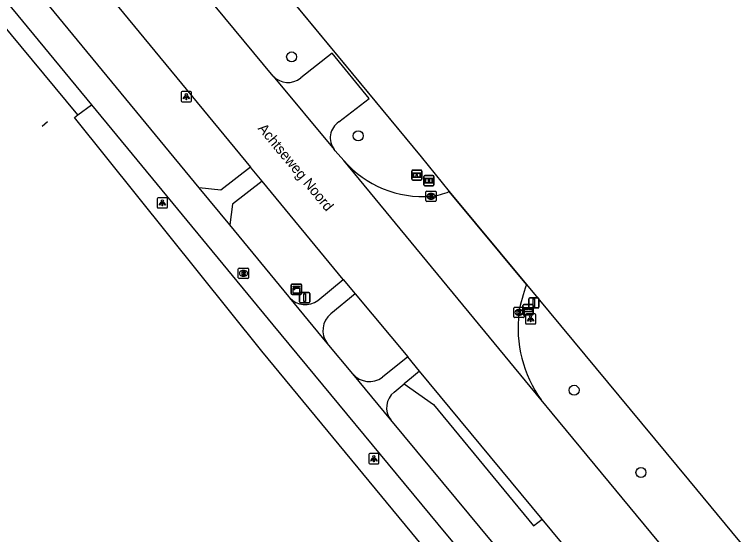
# Model space of a CAD drawing. Extents: x 156141 to 158132, y 385651 to 388399.
# Drawn here: x 157235 to 157305.1, y 386871.2 to 386921.8 of the extents above; entities that cross this region are included whole.
import ezdxf

# ---------------------------------------------------------------- set-up
doc = ezdxf.new("R2010")
doc.units = 0
for name, color, linetype in [('IMGEO_Berm_gesloten', 7, 'Continuous'), ('IMGEO_Berm_groen', 7, 'Continuous'), ('IMGEO_Boom', 7, 'Continuous'), ('IMGEO_Brievenbus', 7, 'Continuous'), ('IMGEO_Fietspad_gesloten', 7, 'Continuous'), ('IMGEO_Fietspad_open', 7, 'Continuous'), ('IMGEO_Groenvoorziening', 7, 'Continuous'), ('IMGEO_Hek', 7, 'Continuous'), ('IMGEO_Informatiebord', 7, 'Continuous'), ('IMGEO_Kast', 7, 'Continuous'), ('IMGEO_Kolk', 7, 'Continuous'), ('IMGEO_Lichtpunt', 7, 'Continuous'), ('IMGEO_Openbare_ruimte_label', 7, 'Continuous'), ('IMGEO_Rijbaan_lokaal_gesloten', 7, 'Continuous'), ('IMGEO_Rijbaan_lokaal_open', 7, 'Continuous'), ('IMGEO_Rioolput', 7, 'Continuous'), ('IMGEO_Verkeersbordpaal', 7, 'Continuous'), ('IMGEO_Voetpad_open', 7, 'Continuous')]:
    doc.layers.add(name, color=color, linetype=linetype)

msp = doc.modelspace()

# ---------------------------------------------------------------- linework, layer by layer
at = {"layer": 'IMGEO_Berm_gesloten'}
msp.add_lwpolyline([(157272.933, 386885.886), (157275.785, 386883.861), (157285.512, 386872.07), (157286.349, 386872.725)], dxfattribs=at)
at = {"layer": 'IMGEO_Berm_groen'}
for points in [[(157241.165, 386912.065), (157168.24, 387000), (157137.214, 387037.654), (157129.348, 387046.654), (157129.178, 387046.529), (157127.008, 387049.143), (157127.143, 387049.253), (157124.865, 387052.05), (157124.727, 387051.938), (157091.865, 387091.792), (157084.853, 387100.371), (157072.384, 387115.628), (157065.427, 387124.277), (157056.488, 387135.39)], [(157257.772, 386928.303), (157274.585, 386907.978), (157277.321, 386904.607)], [(157241.165, 386912.065), (157242.501, 386913.018)], [(157284.844, 386895.533), (157300.587, 386876.543), (157345.88, 386821.789), (157383.128, 386776.761), (157405.264, 386750), (157412.601, 386741.13)]]:
    msp.add_lwpolyline(points, dxfattribs=at)
at = {"layer": 'IMGEO_Boom'}
for centre in [(157261.983, 386917.689), (157268.465, 386910.01), (157289.466, 386885.257), (157295.977, 386877.255)]:
    msp.add_circle(centre, 0.489, dxfattribs=at)
at = {"layer": 'IMGEO_Brievenbus'}
for p, q in [((157284.495, 386892.666), (157284.495, 386893.507)), ((157284.495, 386893.507), (157284.495, 386892.666)), ((157284.57, 386893.591), (157285.411, 386893.591)), ((157285.411, 386893.591), (157284.57, 386893.591)), ((157285.495, 386893.516), (157285.495, 386892.675)), ((157285.495, 386892.675), (157285.495, 386893.516)), ((157284.939, 386893.198), (157284.662, 386893.198)), ((157284.662, 386893.114), (157284.939, 386893.114)), ((157285.331, 386893.198), (157285.054, 386893.198)), ((157285.054, 386893.114), (157285.331, 386893.114)), ((157285.42, 386892.591), (157284.579, 386892.591)), ((157284.579, 386892.591), (157285.42, 386892.591))]:
    msp.add_line(p, q, dxfattribs=at)
msp.add_lwpolyline([(157284.596, 386893.298), (157285.403, 386893.298), (157285.403, 386892.893), (157284.596, 386892.893), (157284.596, 386893.298)], dxfattribs=at)
for centre, radius, start, end in [((157284.573, 386893.513), 0.0779, 92.4484, 184.28452), ((157284.573, 386893.513), 0.0779, 92.4484, 184.28452), ((157285.417, 386893.513), 0.0779, 2.4484, 94.28452), ((157285.417, 386893.513), 0.0779, 2.4484, 94.28452), ((157284.573, 386892.669), 0.0779, 182.4484, 274.28452), ((157284.573, 386892.669), 0.0779, 182.4484, 274.28452), ((157284.692, 386893.156), 0.0519, 125.8089, 234.1911), ((157284.908, 386893.156), 0.0519, 305.8089, 54.1911), ((157285.085, 386893.156), 0.0519, 125.8089, 234.1911), ((157285.301, 386893.156), 0.0519, 305.8089, 54.1911), ((157285.417, 386892.669), 0.0779, 272.4484, 4.28452), ((157285.417, 386892.669), 0.0779, 272.4484, 4.28452)]:
    msp.add_arc(centre, radius, start, end, dxfattribs=at)
at = {"layer": 'IMGEO_Fietspad_gesloten'}
for points in [[(157164.67, 387007.384), (157170.76, 387000), (157242.501, 386913.018)], [(157252.995, 386904.943), (157193.011, 386977.75)], [(157242.501, 386913.018), (157260.151, 386891.618), (157276.215, 386872.22), (157291.723, 386853.572)], [(157255.954, 386901.352), (157252.995, 386904.943)], [(157261.8, 386894.257), (157261.703, 386894.374), (157255.954, 386901.352)], [(157265.439, 386889.847), (157261.8, 386894.257)], [(157267.939, 386886.841), (157265.439, 386889.847)], [(157271.628, 386882.378), (157267.939, 386886.841)], [(157295.329, 386853.774), (157294.671, 386854.555), (157291.271, 386858.658), (157287.92, 386862.757), (157271.628, 386882.378)]]:
    msp.add_lwpolyline(points, dxfattribs=at)
at = {"layer": 'IMGEO_Fietspad_open'}
for points in [[(157257.986, 386906.969), (157255.079, 386904.738), (157252.995, 386904.943)], [(157259.115, 386905.601), (157256.236, 386903.351), (157255.954, 386901.352)]]:
    msp.add_lwpolyline(points, dxfattribs=at)
at = {"layer": 'IMGEO_Groenvoorziening'}
msp.add_lwpolyline([(157288.716, 386853.161), (157259.099, 386889.064), (157240.867, 386911.803), (157241.165, 386912.065)], dxfattribs=at)
at = {"layer": 'IMGEO_Hek'}
for points in [[(157257.646, 386928.455), (157274.585, 386907.978)], [(157237.718, 386910.963), (157238.226, 386911.407)], [(157274.585, 386907.978), (157277.321, 386904.607)], [(157284.844, 386895.533), (157277.321, 386904.607)], [(157284.844, 386895.533), (157300.587, 386876.543)], [(157300.587, 386876.543), (157345.88, 386821.789)]]:
    msp.add_lwpolyline(points, dxfattribs=at)
at = {"layer": 'IMGEO_Informatiebord'}
for p, q in [((157273.768, 386906.688), (157274.558, 386906.688)), ((157274.558, 386906.688), (157273.768, 386906.688)), ((157273.668, 386905.788), (157273.668, 386906.588)), ((157273.668, 386906.588), (157273.668, 386905.788)), ((157274.658, 386906.588), (157274.658, 386905.788)), ((157274.658, 386905.788), (157274.658, 386906.588)), ((157274.845, 386905.256), (157274.845, 386906.056)), ((157274.845, 386906.056), (157274.845, 386905.256)), ((157274.945, 386906.156), (157275.735, 386906.156)), ((157275.735, 386906.156), (157274.945, 386906.156)), ((157275.835, 386906.056), (157275.835, 386905.256)), ((157275.835, 386905.256), (157275.835, 386906.056)), ((157274.558, 386905.688), (157273.768, 386905.688)), ((157273.768, 386905.688), (157274.558, 386905.688)), ((157275.735, 386905.156), (157274.945, 386905.156)), ((157274.945, 386905.156), (157275.735, 386905.156))]:
    msp.add_line(p, q, dxfattribs=at)
for points in [[(157273.769, 386906.42), (157274.557, 386906.42), (157274.557, 386905.956), (157273.769, 386905.956), (157273.769, 386906.42)], [(157273.834, 386906.355), (157273.834, 386906.021), (157274.109, 386906.021), (157274.11, 386906.234), (157274.214, 386906.235), (157274.215, 386906.021), (157274.492, 386906.021), (157274.492, 386906.355), (157274.216, 386906.355), (157274.216, 386906.275), (157274.11, 386906.275), (157274.11, 386906.355), (157273.834, 386906.355)], [(157274.946, 386905.888), (157275.734, 386905.888), (157275.734, 386905.424), (157274.946, 386905.424), (157274.946, 386905.888)], [(157275.011, 386905.823), (157275.011, 386905.489), (157275.286, 386905.489), (157275.287, 386905.702), (157275.391, 386905.703), (157275.392, 386905.489), (157275.669, 386905.489), (157275.669, 386905.823), (157275.393, 386905.823), (157275.393, 386905.743), (157275.287, 386905.743), (157275.287, 386905.823), (157275.011, 386905.823)]]:
    msp.add_lwpolyline(points, dxfattribs=at)
for centre, start, end in [((157273.768, 386906.588), 90, 180), ((157273.768, 386906.588), 90, 180), ((157274.558, 386906.588), 0, 90), ((157274.558, 386906.588), 360, 90), ((157274.945, 386906.056), 90, 180), ((157274.945, 386906.056), 90, 180), ((157275.735, 386906.056), 0, 90), ((157275.735, 386906.056), 360, 90), ((157273.768, 386905.788), 180, 270), ((157273.768, 386905.788), 180, 270), ((157274.558, 386905.788), 270, 0), ((157274.558, 386905.788), 270, 0), ((157274.945, 386905.256), 180, 270), ((157274.945, 386905.256), 180, 270), ((157275.735, 386905.256), 270, 0), ((157275.735, 386905.256), 270, 0)]:
    msp.add_arc(centre, 0.1, start, end, dxfattribs=at)
at = {"layer": 'IMGEO_Kast'}
for p, q in [((157261.943, 386894.665), (157261.943, 386895.506)), ((157261.943, 386895.506), (157261.943, 386894.665)), ((157262.018, 386895.59), (157262.859, 386895.59)), ((157262.859, 386895.59), (157262.018, 386895.59)), ((157262.943, 386895.515), (157262.943, 386894.674)), ((157262.943, 386894.674), (157262.943, 386895.515)), ((157262.868, 386894.59), (157262.027, 386894.59)), ((157262.027, 386894.59), (157262.868, 386894.59))]:
    msp.add_line(p, q, dxfattribs=at)
for points in [[(157262.138, 386895.38), (157262.738, 386895.38), (157262.738, 386895.295), (157262.138, 386895.295), (157262.138, 386895.38)], [(157262.138, 386895.205), (157262.738, 386895.205), (157262.738, 386894.716), (157262.138, 386894.716), (157262.138, 386895.205)]]:
    msp.add_lwpolyline(points, dxfattribs=at)
msp.add_circle((157262.222, 386895.054), 0.0377, dxfattribs=at)
for centre, start, end in [((157262.021, 386895.512), 92.4484, 184.28452), ((157262.021, 386895.512), 92.4484, 184.28452), ((157262.865, 386895.512), 2.4484, 94.28452), ((157262.865, 386895.512), 2.4484, 94.28452), ((157262.021, 386894.668), 182.4484, 274.28452), ((157262.021, 386894.668), 182.4484, 274.28452), ((157262.865, 386894.668), 272.4484, 4.28452), ((157262.865, 386894.668), 272.4484, 4.28452)]:
    msp.add_arc(centre, 0.0779, start, end, dxfattribs=at)
at = {"layer": 'IMGEO_Kolk'}
for p, q in [((157275.049, 386903.709), (157275.049, 386904.561)), ((157275.124, 386904.635), (157275.976, 386904.635)), ((157276.05, 386904.561), (157276.05, 386903.709)), ((157275.56, 386903.855), (157275.535, 386903.855)), ((157275.537, 386904.415), (157275.562, 386904.415)), ((157275.976, 386903.635), (157275.124, 386903.635)), ((157283.685, 386893.331), (157284.537, 386893.331)), ((157283.61, 386892.405), (157283.61, 386893.257)), ((157284.098, 386893.111), (157284.123, 386893.111)), ((157284.611, 386893.257), (157284.611, 386892.405)), ((157284.537, 386892.331), (157283.685, 386892.331)), ((157284.121, 386892.551), (157284.096, 386892.551))]:
    msp.add_line(p, q, dxfattribs=at)
for points in [[(157275.049, 386903.709), (157275.049, 386904.561)], [(157275.124, 386904.635), (157275.976, 386904.635)], [(157276.05, 386904.561), (157276.05, 386903.709)], [(157275.37, 386904.335), (157275.493, 386904.335), (157275.493, 386904.184), (157275.623, 386904.335), (157275.787, 386904.335), (157275.641, 386904.184), (157275.794, 386903.935), (157275.642, 386903.935), (157275.557, 386904.099), (157275.493, 386904.032), (157275.493, 386903.935), (157275.37, 386903.935), (157275.37, 386904.335)], [(157275.976, 386903.635), (157275.124, 386903.635)], [(157283.685, 386893.331), (157284.537, 386893.331)], [(157283.61, 386892.405), (157283.61, 386893.257)], [(157283.931, 386893.031), (157284.054, 386893.031), (157284.054, 386892.88), (157284.184, 386893.031), (157284.348, 386893.031), (157284.202, 386892.88), (157284.355, 386892.631), (157284.203, 386892.631), (157284.118, 386892.795), (157284.054, 386892.728), (157284.054, 386892.631), (157283.931, 386892.631), (157283.931, 386893.031)], [(157284.611, 386893.257), (157284.611, 386892.405)], [(157284.537, 386892.331), (157283.685, 386892.331)]]:
    msp.add_lwpolyline(points, dxfattribs=at)
for centre, start, end in [((157275.126, 386904.559), 91.55205, 178.44795), ((157275.126, 386904.559), 91.55205, 178.44795), ((157275.974, 386904.559), 1.55205, 88.44795), ((157275.974, 386904.559), 1.55205, 88.44795), ((157275.126, 386903.711), 181.55205, 268.44795), ((157275.126, 386903.711), 181.55205, 268.44795), ((157275.974, 386903.711), 271.55205, 358.44795), ((157275.974, 386903.711), 271.55205, 358.44795), ((157283.687, 386893.255), 91.55205, 178.44795), ((157283.687, 386893.255), 91.55205, 178.44795), ((157284.535, 386893.255), 1.55205, 88.44795), ((157284.535, 386893.255), 1.55205, 88.44795), ((157283.687, 386892.407), 181.55205, 268.44795), ((157283.687, 386892.407), 181.55205, 268.44795), ((157284.535, 386892.407), 271.55205, 358.44795), ((157284.535, 386892.407), 271.55205, 358.44795)]:
    msp.add_arc(centre, 0.0765, start, end, dxfattribs=at)
for centre, major_axis, ratio, start_param, end_param in [((157275.536, 386904.135), (-0.387, 0.002), 0.722429, 4.712389, 7.853982), ((157275.561, 386904.135), (-0.39, 0.002), 0.717154, 1.570796, 4.712389), ((157284.097, 386892.831), (-0.387, 0.002), 0.722429, 4.712389, 7.853982), ((157284.122, 386892.831), (-0.39, 0.002), 0.717154, 1.570796, 4.712389)]:
    msp.add_ellipse(centre, major_axis=major_axis, ratio=ratio, start_param=start_param, end_param=end_param, dxfattribs=at)
at = {"layer": 'IMGEO_Lichtpunt'}
for p, q in [((157251.239, 386914.235), (157251.239, 386913.428)), ((157251.239, 386914.235), (157251.239, 386913.428)), ((157252.141, 386914.33), (157251.333, 386914.33)), ((157252.141, 386914.33), (157251.333, 386914.33)), ((157252.235, 386913.428), (157252.235, 386914.235)), ((157252.235, 386913.428), (157252.235, 386914.235)), ((157251.333, 386913.334), (157252.141, 386913.334)), ((157251.333, 386913.334), (157252.141, 386913.334)), ((157248.906, 386903.896), (157248.906, 386903.089)), ((157248.906, 386903.896), (157248.906, 386903.089)), ((157249.808, 386903.991), (157249, 386903.991)), ((157249.808, 386903.991), (157249, 386903.991)), ((157249.902, 386903.089), (157249.902, 386903.896)), ((157249.902, 386903.089), (157249.902, 386903.896)), ((157249, 386902.995), (157249.808, 386902.995)), ((157249, 386902.995), (157249.808, 386902.995)), ((157284.736, 386892.61), (157284.736, 386891.803)), ((157284.736, 386892.61), (157284.736, 386891.803)), ((157285.638, 386892.705), (157284.83, 386892.705)), ((157285.638, 386892.705), (157284.83, 386892.705)), ((157285.732, 386891.803), (157285.732, 386892.61)), ((157285.732, 386891.803), (157285.732, 386892.61)), ((157284.83, 386891.709), (157285.638, 386891.709)), ((157284.83, 386891.709), (157285.638, 386891.709)), ((157269.487, 386879), (157269.487, 386878.193)), ((157269.487, 386879), (157269.487, 386878.193)), ((157270.389, 386879.095), (157269.581, 386879.095)), ((157270.389, 386879.095), (157269.581, 386879.095)), ((157270.483, 386878.193), (157270.483, 386879)), ((157270.483, 386878.193), (157270.483, 386879)), ((157269.581, 386878.099), (157270.389, 386878.099)), ((157269.581, 386878.099), (157270.389, 386878.099))]:
    msp.add_line(p, q, dxfattribs=at)
for points in [[(157251.613, 386913.899), (157251.652, 386913.871), (157251.464, 386913.609), (157251.426, 386913.636), (157251.613, 386913.899)], [(157251.715, 386913.851), (157251.762, 386913.851), (157251.762, 386913.529), (157251.715, 386913.529), (157251.715, 386913.851)], [(157251.825, 386913.871), (157251.863, 386913.898), (157252.05, 386913.636), (157252.011, 386913.608), (157251.825, 386913.871)], [(157249.28, 386903.56), (157249.319, 386903.532), (157249.131, 386903.27), (157249.093, 386903.297), (157249.28, 386903.56)], [(157249.382, 386903.512), (157249.429, 386903.512), (157249.429, 386903.19), (157249.382, 386903.19), (157249.382, 386903.512)], [(157249.492, 386903.532), (157249.53, 386903.559), (157249.717, 386903.297), (157249.678, 386903.269), (157249.492, 386903.532)], [(157285.11, 386892.274), (157285.149, 386892.246), (157284.961, 386891.984), (157284.923, 386892.011), (157285.11, 386892.274)], [(157285.212, 386892.226), (157285.259, 386892.226), (157285.259, 386891.904), (157285.212, 386891.904), (157285.212, 386892.226)], [(157285.322, 386892.246), (157285.36, 386892.273), (157285.547, 386892.011), (157285.508, 386891.983), (157285.322, 386892.246)], [(157269.861, 386878.664), (157269.9, 386878.636), (157269.712, 386878.374), (157269.674, 386878.401), (157269.861, 386878.664)], [(157269.963, 386878.616), (157270.01, 386878.616), (157270.01, 386878.294), (157269.963, 386878.294), (157269.963, 386878.616)], [(157270.073, 386878.636), (157270.111, 386878.663), (157270.298, 386878.401), (157270.259, 386878.373), (157270.073, 386878.636)]]:
    msp.add_lwpolyline(points, dxfattribs=at)
for centre in [(157251.738, 386914.033), (157249.405, 386903.694), (157285.235, 386892.408), (157269.986, 386878.798)]:
    msp.add_circle(centre, 0.0994, dxfattribs=at)
for centre, start, end in [((157251.333, 386914.235), 90, 180), ((157251.333, 386914.235), 90, 180), ((157252.141, 386914.235), 0, 90), ((157252.141, 386914.235), 0, 90), ((157251.333, 386913.428), 180, 270), ((157251.333, 386913.428), 180, 270), ((157252.141, 386913.428), 270, 0), ((157252.141, 386913.428), 270, 360), ((157249, 386903.896), 90, 180), ((157249, 386903.896), 90, 180), ((157249.808, 386903.896), 0, 90), ((157249.808, 386903.896), 0, 90), ((157249, 386903.089), 180, 270), ((157249, 386903.089), 180, 270), ((157249.808, 386903.089), 270, 0), ((157249.808, 386903.089), 270, 360), ((157284.83, 386892.61), 90, 180), ((157284.83, 386892.61), 90, 180), ((157285.638, 386892.61), 0, 90), ((157285.638, 386892.61), 0, 90), ((157284.83, 386891.803), 180, 270), ((157284.83, 386891.803), 180, 270), ((157285.638, 386891.803), 270, 0), ((157285.638, 386891.803), 270, 360), ((157269.581, 386879), 90, 180), ((157269.581, 386879), 90, 180), ((157270.389, 386879), 0, 90), ((157270.389, 386879), 0, 90), ((157269.581, 386878.193), 180, 270), ((157269.581, 386878.193), 180, 270), ((157270.389, 386878.193), 270, 0), ((157270.389, 386878.193), 270, 360)]:
    msp.add_arc(centre, 0.0946, start, end, dxfattribs=at)
at = {"layer": 'IMGEO_Rijbaan_lokaal_gesloten'}
for points in [[(157195.983, 386982.099), (157257.986, 386906.969)], [(157260.189, 386915.832), (157244.022, 386935.339), (157241.867, 386937.946)], [(157260.189, 386915.832), (157266.123, 386908.683)], [(157267.072, 386907.598), (157266.22, 386908.566), (157266.123, 386908.683)], [(157286.267, 386884.319), (157267.072, 386907.598)], [(157259.115, 386905.601), (157257.986, 386906.969)], [(157267.013, 386896.031), (157259.115, 386905.601)], [(157267.013, 386896.031), (157268.159, 386894.645)], [(157268.159, 386894.645), (157273.284, 386888.521)], [(157274.432, 386887.106), (157273.284, 386888.521)], [(157286.349, 386872.725), (157274.432, 386887.106)], [(157304.542, 386862.255), (157287.34, 386883.018), (157286.267, 386884.319)], [(157298.899, 386857.58), (157286.349, 386872.725)]]:
    msp.add_lwpolyline(points, dxfattribs=at)
at = {"layer": 'IMGEO_Rijbaan_lokaal_open'}
for points in [[(157266.574, 386911.363), (157269.513, 386913.654), (157265.941, 386918.061), (157262.862, 386915.645)], [(157277.321, 386904.607), (157284.844, 386895.533)]]:
    msp.add_lwpolyline(points, dxfattribs=at)
for centre, radius, start, end in [((157261.623, 386917.127), 1.932, 222.08115, 309.91519), ((157267.602, 386909.812), 1.86, 123.53058, 217.36455), ((157274.743, 386914.267), 10.165, 221.00242, 274.53007), ((157275.125, 386909.28), 5.163, 274.67384, 295.16891), ((157297.311, 386890.676), 13.38, 158.71511, 170.73159), ((157296.115, 386891.349), 12.1, 172.96663, 215.5236)]:
    msp.add_arc(centre, radius, start, end, dxfattribs=at)
at = {"layer": 'IMGEO_Rioolput'}
for p, q in [((157256.796, 386896.207), (157256.796, 386897.059)), ((157256.871, 386897.133), (157257.723, 386897.133)), ((157257.284, 386896.913), (157257.309, 386896.913)), ((157257.797, 386897.059), (157257.797, 386896.207)), ((157257.723, 386896.133), (157256.871, 386896.133)), ((157257.307, 386896.353), (157257.282, 386896.353))]:
    msp.add_line(p, q, dxfattribs=at)
for points in [[(157256.796, 386896.207), (157256.796, 386897.059)], [(157256.871, 386897.133), (157257.723, 386897.133)], [(157257.385, 386896.831), (157257.133, 386896.833), (157257.133, 386896.433)], [(157257.797, 386897.059), (157257.797, 386896.207)], [(157257.723, 386896.133), (157256.871, 386896.133)], [(157257.133, 386896.433), (157257.257, 386896.433), (157257.257, 386896.595), (157257.268, 386896.595)], [(157257.311, 386896.752), (157257.257, 386896.752), (157257.257, 386896.671)], [(157257.257, 386896.671), (157257.309, 386896.671)], [(157257.315, 386896.566), (157257.386, 386896.433), (157257.526, 386896.433), (157257.461, 386896.559)]]:
    msp.add_lwpolyline(points, dxfattribs=at)
for centre, radius, start, end in [((157256.873, 386897.057), 0.0765, 91.55205, 178.44795), ((157256.873, 386897.057), 0.0765, 91.55205, 178.44795), ((157257.384, 386896.721), 0.109, 350.36119, 89.41601), ((157257.721, 386897.057), 0.0765, 1.55205, 88.44795), ((157257.721, 386897.057), 0.0765, 1.55205, 88.44795), ((157256.873, 386896.209), 0.0765, 181.55205, 268.44795), ((157256.873, 386896.209), 0.0765, 181.55205, 268.44795), ((157257.267, 386896.542), 0.0533, 26.02933, 88.69889), ((157257.293, 386896.86), 0.19, 274.7715, 282.96867), ((157257.317, 386896.656), 0.0964, 77.00612, 93.18647), ((157257.331, 386896.713), 0.0378, 276.66336, 79.67722), ((157257.382, 386896.721), 0.112, 277.58423, 350.98172), ((157257.366, 386896.506), 0.108, 29.51342, 73.79051), ((157257.721, 386896.209), 0.0765, 271.55205, 358.44795), ((157257.721, 386896.209), 0.0765, 271.55205, 358.44795)]:
    msp.add_arc(centre, radius, start, end, dxfattribs=at)
for centre, major_axis, ratio, start_param, end_param in [((157257.283, 386896.633), (-0.387, 0.002), 0.722429, 4.712389, 7.853982), ((157257.308, 386896.633), (-0.39, 0.002), 0.717154, 1.570796, 4.712389)]:
    msp.add_ellipse(centre, major_axis=major_axis, ratio=ratio, start_param=start_param, end_param=end_param, dxfattribs=at)
at = {"layer": 'IMGEO_Verkeersbordpaal'}
for p, q in [((157262.853, 386894.775), (157263.643, 386894.775)), ((157263.643, 386894.775), (157262.853, 386894.775)), ((157262.753, 386893.875), (157262.753, 386894.675)), ((157262.753, 386894.675), (157262.753, 386893.875)), ((157263.743, 386894.675), (157263.743, 386893.875)), ((157263.743, 386893.875), (157263.743, 386894.675)), ((157285.062, 386893.363), (157285.062, 386894.163)), ((157285.062, 386894.163), (157285.062, 386893.363)), ((157285.162, 386894.263), (157285.952, 386894.263)), ((157285.952, 386894.263), (157285.162, 386894.263)), ((157286.052, 386894.163), (157286.052, 386893.363)), ((157286.052, 386893.363), (157286.052, 386894.163)), ((157263.643, 386893.775), (157262.853, 386893.775)), ((157262.853, 386893.775), (157263.643, 386893.775)), ((157285.952, 386893.263), (157285.162, 386893.263)), ((157285.162, 386893.263), (157285.952, 386893.263))]:
    msp.add_line(p, q, dxfattribs=at)
for points in [[(157263.173, 386894.65), (157263.323, 386894.65), (157263.323, 386893.9), (157263.173, 386893.9), (157263.173, 386894.65)], [(157285.482, 386894.138), (157285.632, 386894.138), (157285.632, 386893.388), (157285.482, 386893.388), (157285.482, 386894.138)]]:
    msp.add_lwpolyline(points, dxfattribs=at)
for centre, start, end in [((157262.853, 386894.675), 90, 180), ((157262.853, 386894.675), 90, 180), ((157263.643, 386894.675), 0, 90), ((157263.643, 386894.675), 360, 90), ((157285.162, 386894.163), 90, 180), ((157285.162, 386894.163), 90, 180), ((157285.952, 386894.163), 0, 90), ((157285.952, 386894.163), 360, 90), ((157262.853, 386893.875), 180, 270), ((157262.853, 386893.875), 180, 270), ((157263.643, 386893.875), 270, 0), ((157263.643, 386893.875), 270, 0), ((157285.162, 386893.363), 180, 270), ((157285.162, 386893.363), 180, 270), ((157285.952, 386893.363), 270, 0), ((157285.952, 386893.363), 270, 0)]:
    msp.add_arc(centre, 0.1, start, end, dxfattribs=at)
at = {"layer": 'IMGEO_Voetpad_open'}
for points in [[(157264.532, 386894.007), (157267.013, 386896.031)], [(157268.159, 386894.645), (157265.787, 386892.69)], [(157273.284, 386888.521), (157270.815, 386886.519)], [(157274.432, 386887.106), (157273.64, 386886.461), (157272.933, 386885.886)], [(157271.95, 386885.086), (157272.933, 386885.886)]]:
    msp.add_lwpolyline(points, dxfattribs=at)
for centre, radius, start, end in [((157263.3, 386895.594), 2.009, 221.70699, 307.83608), ((157267.093, 386891.087), 2.067, 129.17842, 216.86433), ((157269.551, 386888.235), 2.131, 220.84969, 306.37372), ((157273.177, 386883.567), 1.953, 128.92788, 217.51007)]:
    msp.add_arc(centre, radius, start, end, dxfattribs=at)

# ---------------------------------------------------------------- texts
at = {"layer": 'IMGEO_Openbare_ruimte_label'}
msp.add_text('Achtseweg Noord', height=1, rotation=309.64417, dxfattribs=at).set_placement((157258.639, 386910.706))

doc.saveas('drawing.dxf')
